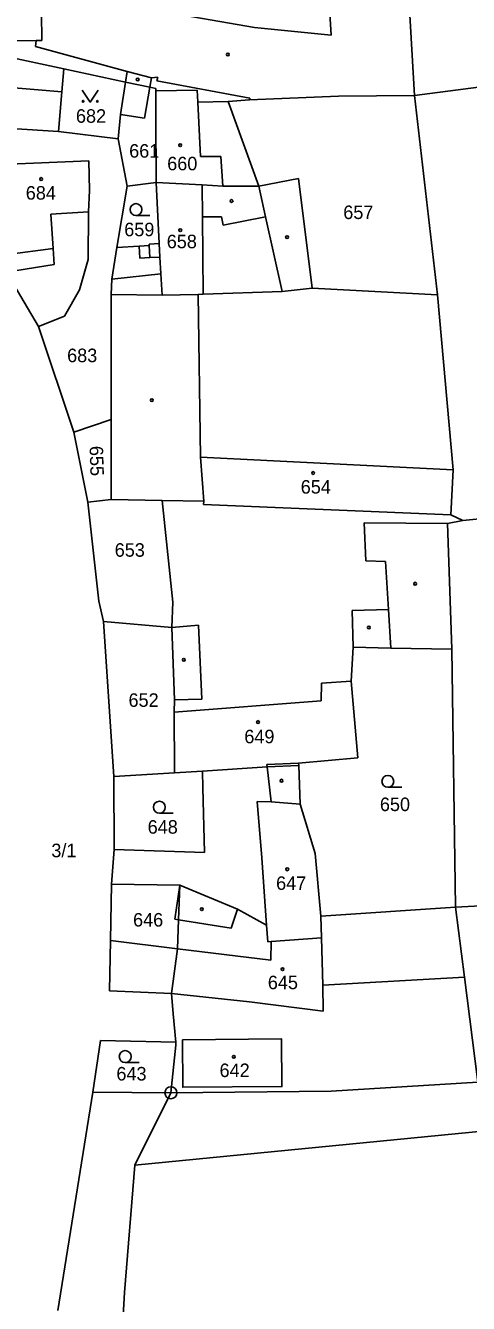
# Model space of a CAD drawing. Extents: x -779596 to -776743, y -1030330 to -1024513.
# Drawn here: x -777734.7 to -777678.9, y -1025206.5 to -1025045.8 of the extents above; entities that cross this region are included whole.
import ezdxf

# ---------------------------------------------------------------- set-up
doc = ezdxf.new("R2010")
doc.units = 0
for name, color, linetype in [('hranice parcel', 7, 'Continuous'), ('hranice vnitřní', 7, 'Continuous'), ('kultura', 7, 'Continuous'), ('Kód', 7, 'Continuous'), ('č_pacel stav_', 7, 'Continuous'), ('č_parcel poz_', 7, 'Continuous')]:
    doc.layers.add(name, color=color, linetype=linetype)

msp = doc.modelspace()

# ---------------------------------------------------------------- linework, layer by layer
at = {"layer": 'hranice parcel'}
for points in [[(-777686.75, -1025036.49), (-777685.71, -1025054.61)], [(-777741.43, -1025048.78), (-777729.86, -1025051.26)], [(-777730.11, -1025054.15), (-777729.86, -1025051.26)], [(-777729.86, -1025051.26), (-777722.11, -1025052.92)], [(-777722.75, -1025056.99), (-777722.11, -1025052.92)], [(-777722.11, -1025052.92), (-777719.03, -1025053.58)], [(-777685.71, -1025054.61), (-777672.5, -1025052.88)], [(-777730.53, -1025059.14), (-777730.11, -1025054.15)], [(-777719.03, -1025053.58), (-777718.3, -1025053.73)], [(-777718.3, -1025054.04), (-777718.3, -1025053.73)], [(-777718.3, -1025054.04), (-777713.07, -1025053.93)], [(-777718.3, -1025054.04), (-777718.29, -1025056.97)], [(-777713.07, -1025053.93), (-777712.99, -1025055.43)], [(-777706.47, -1025055.16), (-777695.3, -1025054.7)], [(-777695.3, -1025054.7), (-777685.71, -1025054.61)], [(-777685.71, -1025054.61), (-777682.8, -1025079.7)], [(-777712.99, -1025055.43), (-777709.16, -1025055.35)], [(-777709.16, -1025055.35), (-777706.47, -1025055.16)], [(-777709.16, -1025055.35), (-777705.3, -1025066.02)], [(-777746.37, -1025058.14), (-777730.53, -1025059.14)], [(-777723.04, -1025060.06), (-777722.75, -1025056.99)], [(-777718.29, -1025056.97), (-777718.26, -1025065.56)], [(-777730.53, -1025059.14), (-777723.04, -1025060.06)], [(-777723.04, -1025060.06), (-777721.91, -1025066.03)], [(-777737.68, -1025063.27), (-777726.73, -1025062.84)], [(-777726.73, -1025062.84), (-777726.63, -1025066.56)], [(-777723.18, -1025073.71), (-777721.91, -1025066.03)], [(-777721.91, -1025066.03), (-777718.26, -1025065.56)], [(-777718.26, -1025065.56), (-777717.85, -1025073.24)], [(-777718.26, -1025065.56), (-777712.46, -1025065.86)], [(-777712.46, -1025065.86), (-777709.83, -1025066)], [(-777709.83, -1025066), (-777705.3, -1025066.02)], [(-777705.3, -1025066.02), (-777700.33, -1025065.07)], [(-777705.3, -1025066.02), (-777704.46, -1025069.87)], [(-777700.33, -1025065.07), (-777698.58, -1025078.86)], [(-777726.78, -1025069.25), (-777726.63, -1025066.56)], [(-777726.79, -1025075.23), (-777726.78, -1025069.25)], [(-777704.46, -1025069.87), (-777702.39, -1025079.28)], [(-777723.82, -1025077.73), (-777723.18, -1025073.71)], [(-777720.39, -1025073.57), (-777719.14, -1025073.46)], [(-777720.39, -1025073.57), (-777720.3, -1025075.07)], [(-777719.14, -1025073.31), (-777717.85, -1025073.24)], [(-777719.14, -1025073.46), (-777719.14, -1025073.31)], [(-777727.9, -1025079.07), (-777726.79, -1025075.23)], [(-777720.3, -1025075.07), (-777719.05, -1025075)], [(-777719.05, -1025075), (-777717.76, -1025074.93)], [(-777717.76, -1025074.93), (-777717.65, -1025077.03)], [(-777737.1, -1025076.81), (-777733.04, -1025083.67)], [(-777723.82, -1025077.73), (-777717.65, -1025077.03)], [(-777729.79, -1025082.36), (-777727.9, -1025079.07)], [(-777723.89, -1025079.63), (-777723.82, -1025077.73)], [(-777698.58, -1025078.86), (-777682.8, -1025079.7)], [(-777723.9, -1025095.35), (-777723.89, -1025079.63)], [(-777723.89, -1025079.63), (-777717.5, -1025079.72)], [(-777717.5, -1025079.72), (-777712.94, -1025079.62)], [(-777712.94, -1025079.62), (-777712.31, -1025079.6)], [(-777712.31, -1025079.6), (-777702.39, -1025079.28)], [(-777682.8, -1025079.7), (-777680.85, -1025101.68)], [(-777733.04, -1025083.67), (-777729.79, -1025082.36)], [(-777733.04, -1025083.67), (-777728.62, -1025096.96)], [(-777728.62, -1025096.96), (-777723.9, -1025095.35)], [(-777723.9, -1025105.42), (-777723.9, -1025095.35)], [(-777728.62, -1025096.96), (-777726.86, -1025105.76)], [(-777681.14, -1025107.36), (-777680.85, -1025101.68)], [(-777726.86, -1025105.76), (-777723.9, -1025105.42)], [(-777726.86, -1025105.76), (-777725.47, -1025118.21)], [(-777723.9, -1025105.42), (-777717.48, -1025105.55)], [(-777717.48, -1025105.55), (-777712.25, -1025105.65)], [(-777717.48, -1025105.55), (-777716.14, -1025118.35)], [(-777712.27, -1025106.03), (-777712.25, -1025105.65)], [(-777712.27, -1025106.03), (-777681.14, -1025107.36)], [(-777681.56, -1025108.46), (-777679.64, -1025108.07)], [(-777681.14, -1025107.36), (-777679.64, -1025108.07)], [(-777679.64, -1025108.07), (-777668.73, -1025106.99)], [(-777681.56, -1025108.46), (-777681, -1025124.24)], [(-777725.47, -1025118.21), (-777724.88, -1025120.76)], [(-777716.27, -1025121.53), (-777716.14, -1025118.35)], [(-777724.88, -1025120.76), (-777723.56, -1025140.25)], [(-777724.88, -1025120.76), (-777716.27, -1025121.53)], [(-777716.27, -1025121.53), (-777715.94, -1025130.6)], [(-777693.7, -1025128.28), (-777693.44, -1025124.01)], [(-777693.44, -1025124.01), (-777688.7, -1025124.1)], [(-777688.7, -1025124.1), (-777681, -1025124.24)], [(-777681, -1025124.24), (-777680.55, -1025156.71)], [(-777693.7, -1025128.28), (-777692.86, -1025137.91)], [(-777715.96, -1025132.18), (-777715.94, -1025130.6)], [(-777715.96, -1025132.18), (-777715.95, -1025139.5)], [(-777700.31, -1025138.57), (-777692.86, -1025137.91)], [(-777700.31, -1025138.57), (-777700.28, -1025138.87)], [(-777723.56, -1025140.25), (-777715.95, -1025139.8)], [(-777715.95, -1025139.5), (-777715.95, -1025139.8)], [(-777715.95, -1025139.8), (-777712.42, -1025139.59)], [(-777712.42, -1025139.59), (-777704.28, -1025139.03)], [(-777712.42, -1025139.59), (-777712.37, -1025141.67)], [(-777704.28, -1025139.03), (-777700.28, -1025138.87)], [(-777700.28, -1025138.87), (-777700.09, -1025143.72)], [(-777723.56, -1025140.25), (-777723.53, -1025149.44)], [(-777712.37, -1025141.67), (-777712.16, -1025149.83)], [(-777700.09, -1025143.72), (-777698.23, -1025149.93)], [(-777723.85, -1025153.79), (-777723.53, -1025149.44)], [(-777723.53, -1025149.44), (-777712.16, -1025149.83)], [(-777698.23, -1025149.93), (-777697.51, -1025157.83)], [(-777724, -1025160.9), (-777723.85, -1025153.79)], [(-777723.85, -1025153.79), (-777715.24, -1025153.94)], [(-777715.42, -1025158.3), (-777715.24, -1025153.94)], [(-777715.24, -1025153.94), (-777708.02, -1025156.96)], [(-777680.55, -1025156.71), (-777665.41, -1025155.9)], [(-777708.02, -1025156.96), (-777704.33, -1025158.95)], [(-777697.51, -1025157.83), (-777680.55, -1025156.71)], [(-777697.51, -1025157.83), (-777697.43, -1025160.54)], [(-777680.55, -1025156.71), (-777679.42, -1025165.49)], [(-777715.57, -1025161.93), (-777715.42, -1025158.3)], [(-777704.33, -1025158.95), (-777704.18, -1025161.04)], [(-777724.13, -1025167.23), (-777724, -1025160.9)], [(-777724, -1025160.9), (-777715.57, -1025161.93)], [(-777704.18, -1025161.04), (-777703.76, -1025161.01)], [(-777703.76, -1025161.01), (-777697.43, -1025160.54)], [(-777697.43, -1025160.54), (-777697.27, -1025166.51)], [(-777679.42, -1025165.49), (-777677.72, -1025178.71)], [(-777724.13, -1025167.23), (-777716.32, -1025167.56)], [(-777697.27, -1025166.51), (-777697.22, -1025169.76)], [(-777716.32, -1025167.56), (-777706.48, -1025168.62)], [(-777716.32, -1025167.56), (-777716.08, -1025170.09)], [(-777706.48, -1025168.62), (-777697.22, -1025169.76)], [(-777716.08, -1025170.09), (-777715.75, -1025173.69)], [(-777726.21, -1025179.94), (-777725.24, -1025173.48)], [(-777725.24, -1025173.48), (-777715.75, -1025173.69)], [(-777715.78, -1025174.05), (-777715.75, -1025173.69)], [(-777716.39, -1025180.04), (-777715.78, -1025174.05)], [(-777696.22, -1025179.85), (-777677.72, -1025178.71)], [(-777730.63, -1025207.41), (-777726.21, -1025179.94)], [(-777726.21, -1025179.94), (-777716.39, -1025180.04)], [(-777720.94, -1025189.16), (-777716.39, -1025180.04)], [(-777716.39, -1025180.04), (-777696.22, -1025179.85)], [(-777720.94, -1025189.16), (-777663, -1025183.5)], [(-777722.23, -1025205.16), (-777720.94, -1025189.16)], [(-777724.2, -1025239.45), (-777722.23, -1025205.16)]]:
    msp.add_lwpolyline(points, dxfattribs=at)
at = {"layer": 'hranice vnitřní'}
for points in [[(-777696.79, -1025037.5), (-777696.19, -1025047.02)], [(-777732.72, -1025040.79), (-777732.62, -1025047.69)], [(-777717.98, -1025043.98), (-777705.86, -1025046.07)], [(-777705.86, -1025046.07), (-777696.19, -1025047.02)], [(-777750.46, -1025047.94), (-777733.35, -1025047.7)], [(-777733.42, -1025048.44), (-777733.35, -1025047.7)], [(-777733.42, -1025048.44), (-777721.9, -1025051.59)], [(-777733.35, -1025047.7), (-777732.62, -1025047.69)], [(-777722.11, -1025052.92), (-777721.9, -1025051.59)], [(-777721.9, -1025051.59), (-777718.83, -1025052.41)], [(-777741.6, -1025053.2), (-777730.11, -1025054.15)], [(-777719.03, -1025053.58), (-777718.83, -1025052.41)], [(-777718.83, -1025052.41), (-777718.05, -1025052.29)], [(-777718.15, -1025052.75), (-777718.05, -1025052.29)], [(-777718.15, -1025052.75), (-777706.44, -1025054.95)], [(-777719.69, -1025057.47), (-777719.03, -1025053.58)], [(-777706.47, -1025055.16), (-777706.44, -1025054.95)], [(-777712.99, -1025055.43), (-777712.64, -1025062.28)], [(-777722.75, -1025056.99), (-777719.69, -1025057.47)], [(-777712.64, -1025062.28), (-777710.09, -1025062.29)], [(-777710.09, -1025062.29), (-777709.83, -1025066)], [(-777712.46, -1025065.86), (-777712.41, -1025069.88)], [(-777731.5, -1025069.53), (-777726.78, -1025069.25)], [(-777731.5, -1025069.53), (-777731.22, -1025073.87)], [(-777712.41, -1025069.88), (-777710.01, -1025069.86)], [(-777712.41, -1025069.88), (-777712.31, -1025079.6)], [(-777710.01, -1025069.86), (-777709.79, -1025070.91)], [(-777709.79, -1025070.91), (-777704.46, -1025069.87)], [(-777736.94, -1025074.61), (-777731.22, -1025073.87)], [(-777731.22, -1025073.87), (-777731.09, -1025075.86)], [(-777723.18, -1025073.71), (-777720.39, -1025073.57)], [(-777719.14, -1025073.46), (-777719.05, -1025075)], [(-777717.85, -1025073.24), (-777717.76, -1025074.93)], [(-777737.1, -1025076.81), (-777731.09, -1025075.86)], [(-777717.65, -1025077.03), (-777717.5, -1025079.72)], [(-777702.39, -1025079.28), (-777698.58, -1025078.86)], [(-777712.94, -1025079.62), (-777712.67, -1025100.08)], [(-777712.67, -1025100.08), (-777712.25, -1025105.65)], [(-777712.67, -1025100.08), (-777680.85, -1025101.68)], [(-777692.07, -1025108.35), (-777691.86, -1025113.15)], [(-777692.07, -1025108.35), (-777681.56, -1025108.46)], [(-777691.86, -1025113.15), (-777689.38, -1025113.23)], [(-777689.38, -1025113.23), (-777689, -1025119.27)], [(-777693.57, -1025119.4), (-777689, -1025119.27)], [(-777689, -1025119.27), (-777688.7, -1025124.1)], [(-777693.57, -1025119.4), (-777693.44, -1025124.01)], [(-777716.27, -1025121.53), (-777712.9, -1025121.24)], [(-777712.9, -1025121.24), (-777712.48, -1025130.54)], [(-777697.45, -1025130.73), (-777697.42, -1025128.54)], [(-777697.42, -1025128.54), (-777693.7, -1025128.28)], [(-777715.94, -1025130.6), (-777712.48, -1025130.54)], [(-777715.96, -1025132.18), (-777697.45, -1025130.73)], [(-777704.31, -1025138.73), (-777700.31, -1025138.57)], [(-777704.31, -1025138.73), (-777704.28, -1025139.03)], [(-777704.28, -1025139.03), (-777703.75, -1025143.45)], [(-777705.51, -1025143.42), (-777704.95, -1025150.5)], [(-777705.51, -1025143.42), (-777703.75, -1025143.45)], [(-777703.75, -1025143.45), (-777700.09, -1025143.72)], [(-777704.95, -1025150.5), (-777704.33, -1025158.95)], [(-777715.91, -1025158.22), (-777715.24, -1025153.94)], [(-777708.8, -1025159.34), (-777708.02, -1025156.96)], [(-777715.91, -1025158.22), (-777715.42, -1025158.3)], [(-777715.42, -1025158.3), (-777708.8, -1025159.34)], [(-777703.8, -1025163.36), (-777703.76, -1025161.01)], [(-777716.32, -1025167.56), (-777715.57, -1025161.93)], [(-777715.57, -1025161.93), (-777703.8, -1025163.36)], [(-777697.27, -1025166.51), (-777679.42, -1025165.49)], [(-777714.94, -1025173.36), (-777714.89, -1025179.35), (-777702.4, -1025179.26), (-777702.45, -1025173.26), (-777714.94, -1025173.36)]]:
    msp.add_lwpolyline(points, dxfattribs=at)
at = {"layer": 'kultura'}
for points in [[(-777727.54, -1025053.94), (-777726.54, -1025055.44), (-777725.54, -1025053.94)], [(-777720.78, -1025069.71), (-777719.03, -1025069.71)], [(-777689.07, -1025141.62), (-777687.32, -1025141.62)], [(-777717.84, -1025144.87), (-777716.09, -1025144.87)], [(-777722.14, -1025176.24), (-777720.39, -1025176.24)]]:
    msp.add_lwpolyline(points, dxfattribs=at)
for centre, radius in [((-777709.21, -1025049.46), 0.175), ((-777720.57, -1025052.6), 0.175), ((-777727.44, -1025055.34), 0.1), ((-777725.64, -1025055.34), 0.1), ((-777715.21, -1025060.87), 0.175), ((-777732.73, -1025065.12), 0.175), ((-777708.74, -1025067.88), 0.175), ((-777720.78, -1025068.96), 0.75), ((-777715.2, -1025071.55), 0.175), ((-777701.76, -1025072.42), 0.175), ((-777718.8, -1025092.92), 0.175), ((-777698.48, -1025102.09), 0.175), ((-777685.64, -1025116.01), 0.175), ((-777691.46, -1025121.52), 0.175), ((-777714.76, -1025125.59), 0.175), ((-777705.42, -1025133.41), 0.175), ((-777689.07, -1025140.87), 0.75), ((-777702.45, -1025140.79), 0.175), ((-777717.84, -1025144.12), 0.75), ((-777701.73, -1025151.93), 0.175), ((-777712.49, -1025156.94), 0.175), ((-777702.33, -1025164.49), 0.175), ((-777722.14, -1025175.49), 0.75), ((-777708.46, -1025175.52), 0.175)]:
    msp.add_circle(centre, radius, dxfattribs=at)
at = {"layer": 'Kód'}
for radius in [0.75, 0.032]:
    msp.add_circle((-777716.39, -1025180.04), radius, dxfattribs=at)

# ---------------------------------------------------------------- texts
at = {"layer": 'č_pacel stav_'}
for s, p in [('660', (-777716.85, -1025064.02)), ('684', (-777734.66, -1025067.71)), ('658', (-777716.91, -1025073.82)), ('654', (-777700.04, -1025104.68)), ('649', (-777707.14, -1025136.08)), ('647', (-777703.14, -1025154.52)), ('645', (-777704.18, -1025167.01)), ('642', (-777710.259, -1025178.06))]:
    msp.add_text(s, height=1.7, dxfattribs=at).set_placement(p)
at = {"layer": 'č_parcel poz_'}
for s, p in [('682', (-777728.34, -1025058.04)), ('661', (-777721.64, -1025062.43)), ('657', (-777694.68, -1025070.15)), ('659', (-777722.26, -1025072.31)), ('683', (-777729.45, -1025088.15)), ('653', (-777723.46, -1025112.62)), ('652', (-777721.72, -1025131.5)), ('650', (-777690.07, -1025144.61)), ('648', (-777719.31, -1025147.45)), ('3/1', (-777731.44, -1025150.41)), ('646', (-777721.15, -1025159.13)), ('643', (-777723.25, -1025178.49))]:
    msp.add_text(s, height=1.7, dxfattribs=at).set_placement(p)
msp.add_text('655', height=1.7, rotation=271.90216, dxfattribs=at).set_placement((-777726.634, -1025098.703))

doc.saveas('drawing.dxf')
